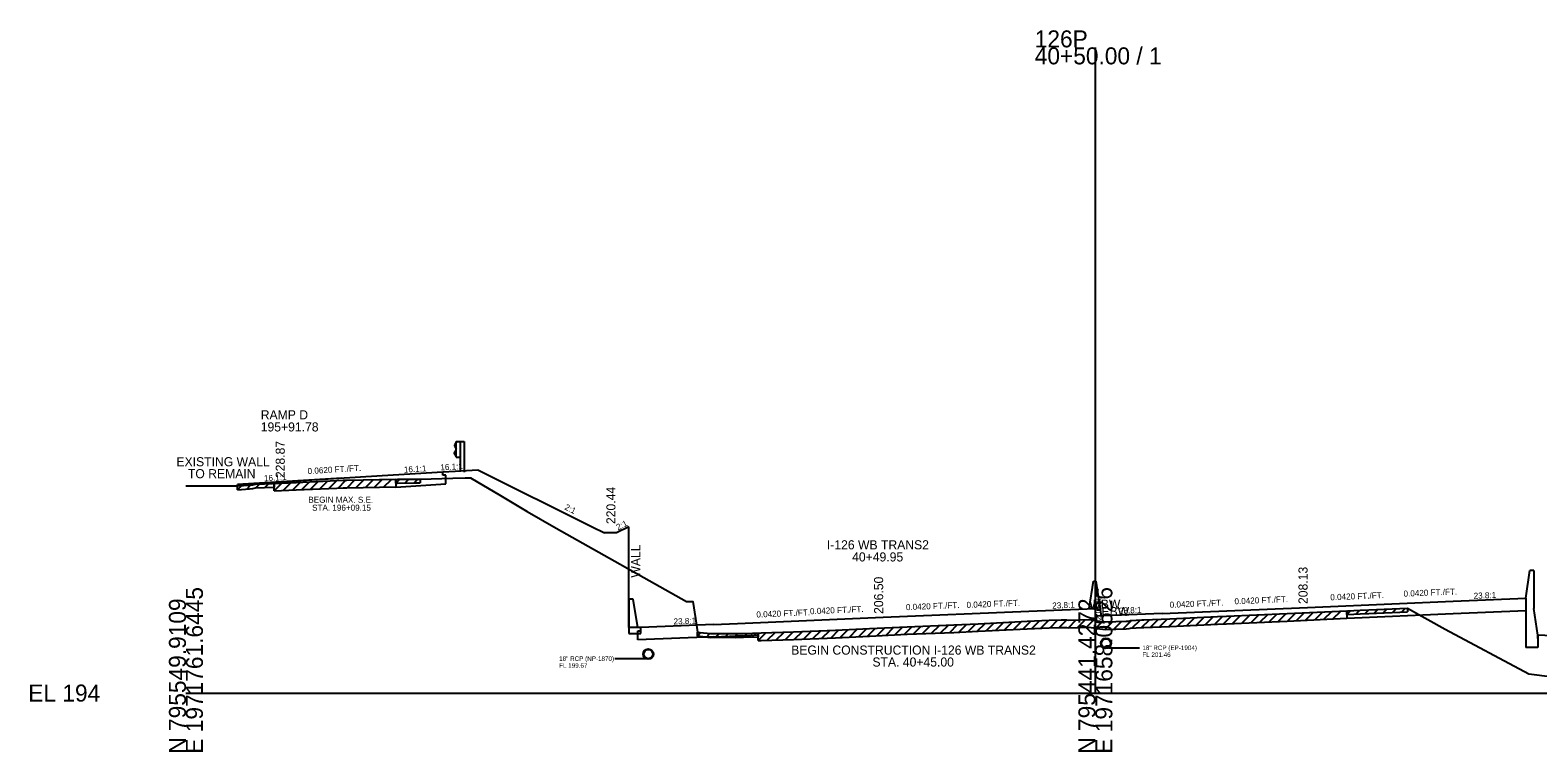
# Model space of a CAD drawing. Extents: x -161 to 1970889, y -4362 to 797231.
# Drawn here: x 974.3 to 1223, y 2990.3 to 3109.3 of the extents above; entities that cross this region are included whole.
import ezdxf

# ---------------------------------------------------------------- set-up
doc = ezdxf.new("R2010")
doc.units = 0
for name, color, linetype in [('RD_GPK_XS_Cell', 7, 'Continuous'), ('RD_XS_Base', 7, 'Continuous'), ('RD_XS_Box', 7, 'Continuous'), ('RD_XS_EarthShd', 7, 'Continuous'), ('RD_XS_ExGround', 7, 'Continuous'), ('RD_XS_ExPaveRet', 7, 'Continuous'), ('RD_XS_GR', 7, 'Continuous'), ('RD_XS_MedBWall', 7, 'Continuous'), ('RD_XS_Misc_Line', 7, 'Continuous'), ('RD_XS_Pave', 7, 'Continuous'), ('RD_XS_PaveOvlay', 7, 'Continuous'), ('RD_XS_PaveShd', 7, 'Continuous'), ('RD_XS_Pipe', 7, 'Continuous'), ('RD_XS_TieSlope', 7, 'Continuous'), ('RD_XS_TX_Elev_EX', 7, 'Continuous'), ('RD_XS_TX_Elev_PR', 7, 'Continuous'), ('RD_XS_TX_Misc', 7, 'Continuous'), ('RD_XS_TX_MkPT', 7, 'Continuous'), ('RD_XS_TX_Notes', 7, 'Continuous'), ('RD_XS_TX_Profile', 7, 'Continuous'), ('RD_XS_TX_ShdSlope', 7, 'Continuous'), ('RD_XS_TX_Slope', 7, 'Continuous'), ('RD_XS_TX_Station', 7, 'Continuous')]:
    doc.layers.add(name, color=color, linetype=linetype)

msp = doc.modelspace()

# ---------------------------------------------------------------- linework, layer by layer
at = {"layer": 'RD_GPK_XS_Cell'}
for p, q in [((1150, 3000), (1150, 3106.48)), ((1000, 3000), (1150, 3000)), ((1150, 3000), (1300, 3000))]:
    msp.add_line(p, q, dxfattribs=at)
at = {"layer": 'RD_XS_Base'}
for p, q in [((1042.39, 3035.93), (1042.39, 3036.49)), ((1008.53, 3034.17), (1008.53, 3034.38)), ((1034.62, 3033.96), (1042.89, 3034.48)), ((1042.89, 3035.96), (1042.39, 3035.93)), ((1042.89, 3034.48), (1042.89, 3035.96)), ((1191.46, 3012.36), (1209, 3013.1)), ((1209, 3013.1), (1221, 3013.6)), ((1074.53, 3010.24), (1075.03, 3010.26)), ((1074.53, 3008.76), (1074.53, 3010.24)), ((1087.04, 3009.28), (1074.53, 3008.76)), ((1075.03, 3010.26), (1075.03, 3010.82)), ((1087.04, 3009.28), (1091, 3009.45)), ((1091, 3009.45), (1094.36, 3009.59)), ((1222.98, 3008.99), (1222.98, 3009.55))]:
    msp.add_line(p, q, dxfattribs=at)
at = {"layer": 'RD_XS_Box'}
for p, q in [((1073.03, 3010.82), (1073.03, 3027.44)), ((1075.03, 3010.82), (1073.03, 3010.82))]:
    msp.add_line(p, q, dxfattribs=at)
at = {"layer": 'RD_XS_EarthShd'}
msp.add_line((1042.39, 3036.49), (1044.4, 3036.61), dxfattribs=at)
at = {"layer": 'RD_XS_ExGround'}
msp.add_lwpolyline([(1000, 3034.18), (1008.53, 3034.17), (1010.48, 3034.31), (1011.06, 3034.35), (1011.45, 3034.44), (1012.95, 3034.52), (1018.17, 3034.75), (1024.87, 3035.06), (1025.96, 3035.1), (1026.54, 3035.11), (1034.89, 3035.25), (1037.57, 3035.29), (1038.64, 3035.3), (1044.03, 3035.44), (1046.04, 3035.49), (1046.96, 3035.49), (1051.89, 3032.57), (1056.28, 3029.94), (1061.08, 3027.22), (1082.56, 3015.1), (1083.61, 3015.1), (1084.05, 3012.3), (1084.36, 3010.02), (1084.84, 3009.98), (1086.5, 3009.8), (1086.75, 3009.85), (1087.79, 3009.84), (1090.64, 3009.81), (1091.95, 3009.84), (1094.89, 3009.91), (1100.2, 3010.11), (1107.11, 3010.37), (1112.72, 3010.64), (1118.96, 3010.94), (1126.68, 3011.26), (1130.69, 3011.44), (1138.75, 3011.84), (1142.4, 3012.02), (1144.36, 3012.06), (1145.22, 3012.07), (1145.51, 3012.03), (1147.19, 3012.07), (1148.97, 3012.12), (1150, 3011.96), (1150.32, 3011.91), (1151.67, 3011.72), (1155.09, 3011.86), (1155.56, 3011.88), (1155.79, 3011.96), (1157.65, 3012.05), (1157.98, 3012.06), (1162.3, 3012.25), (1170.15, 3012.6), (1171.63, 3012.67), (1181.65, 3013.13), (1191.58, 3013.58), (1193.68, 3013.68), (1195.1, 3013.74), (1201.46, 3014.02), (1207.7, 3010.56), (1221.47, 3003.19), (1225.42, 3002.68)], dxfattribs=at)
at = {"layer": 'RD_XS_ExPaveRet'}
for p, q in [((1008.53, 3033.54), (1008.53, 3034.17)), ((1011.06, 3033.72), (1011.45, 3033.82)), ((1011.45, 3033.82), (1012.95, 3033.9)), ((1012.95, 3033.9), (1014.55, 3033.97)), ((1014.55, 3033.34), (1014.55, 3034.59)), ((1014.55, 3034.59), (1014.55, 3033.97)), ((1018.17, 3033.5), (1024.87, 3033.81)), ((1024.87, 3033.81), (1025.96, 3033.85)), ((1025.96, 3033.85), (1026.54, 3033.86)), ((1026.54, 3033.86), (1034.62, 3034)), ((1034.62, 3035.25), (1034.62, 3034)), ((1034.62, 3034.62), (1034.62, 3035.25)), ((1034.62, 3034.62), (1034.89, 3034.63)), ((1034.89, 3034.63), (1037.57, 3034.66)), ((1037.57, 3034.66), (1038.64, 3034.67)), ((1038.64, 3035.3), (1038.64, 3034.67)), ((1008.53, 3033.54), (1010.48, 3033.69)), ((1010.48, 3033.69), (1011.06, 3033.72)), ((1014.55, 3033.34), (1018.17, 3033.5)), ((1201.46, 3014.02), (1201.46, 3013.4)), ((1170.15, 3011.35), (1171.63, 3011.42)), ((1171.63, 3011.42), (1181.65, 3011.88)), ((1181.65, 3011.88), (1191.46, 3012.33)), ((1191.46, 3013.58), (1191.46, 3012.33)), ((1191.46, 3012.95), (1191.46, 3013.58)), ((1191.46, 3012.95), (1191.58, 3012.96)), ((1191.58, 3012.96), (1193.68, 3013.05)), ((1193.68, 3013.05), (1195.1, 3013.11)), ((1195.1, 3013.11), (1201.46, 3013.4)), ((1084.36, 3009.4), (1084.36, 3010.02)), ((1084.36, 3009.4), (1084.84, 3009.36)), ((1084.84, 3009.36), (1086.5, 3009.17)), ((1086.5, 3009.17), (1086.75, 3009.22)), ((1086.75, 3009.22), (1087.79, 3009.22)), ((1087.79, 3009.22), (1090.64, 3009.18)), ((1090.64, 3009.18), (1091.95, 3009.22)), ((1091.95, 3009.22), (1094.36, 3009.27)), ((1094.36, 3008.65), (1094.36, 3009.9)), ((1094.36, 3009.9), (1094.36, 3009.27)), ((1100.2, 3008.86), (1107.11, 3009.12)), ((1107.11, 3009.12), (1112.72, 3009.39)), ((1112.72, 3009.39), (1118.96, 3009.69)), ((1118.96, 3009.69), (1126.68, 3010.01)), ((1126.68, 3010.01), (1130.69, 3010.19)), ((1130.69, 3010.19), (1138.75, 3010.59)), ((1138.75, 3010.59), (1142.4, 3010.77)), ((1142.4, 3010.77), (1144.36, 3010.81)), ((1144.36, 3010.81), (1145.22, 3010.82)), ((1145.22, 3010.82), (1145.51, 3010.78)), ((1145.51, 3010.78), (1147.19, 3010.82)), ((1147.19, 3010.82), (1148.97, 3010.87)), ((1148.97, 3010.87), (1150, 3010.71)), ((1150, 3010.71), (1150.32, 3010.66)), ((1150.32, 3010.66), (1151.67, 3010.47)), ((1151.67, 3010.47), (1155.09, 3010.61)), ((1155.09, 3010.61), (1155.56, 3010.63)), ((1155.56, 3010.63), (1155.79, 3010.71)), ((1155.79, 3010.71), (1157.65, 3010.8)), ((1157.65, 3010.8), (1157.98, 3010.81)), ((1157.98, 3010.81), (1162.3, 3011)), ((1162.3, 3011), (1170.15, 3011.35)), ((1094.36, 3008.65), (1094.89, 3008.66)), ((1094.89, 3008.66), (1100.2, 3008.86))]:
    msp.add_line(p, q, dxfattribs=at)
at = {"layer": 'RD_XS_GR'}
for p, q in [((1044.55, 3041.32), (1044.28, 3040.88)), ((1044.55, 3041.48), (1045.21, 3041.48)), ((1044.55, 3038.92), (1044.55, 3041.48)), ((1045.21, 3041.48), (1045.88, 3041.48)), ((1045.21, 3041.48), (1045.21, 3036.54)), ((1045.88, 3041.48), (1045.88, 3036.43)), ((1044.28, 3040.88), (1044.28, 3040.77)), ((1044.28, 3040.77), (1044.55, 3040.33)), ((1044.28, 3039.63), (1044.55, 3040.07)), ((1044.28, 3039.52), (1044.28, 3039.63)), ((1044.55, 3039.08), (1044.28, 3039.52)), ((1044.55, 3038.92), (1045.21, 3038.92))]:
    msp.add_line(p, q, dxfattribs=at)
at = {"layer": 'RD_XS_MedBWall'}
for p, q in [((1221, 3015.64), (1221.67, 3020.19)), ((1222.33, 3020.19), (1221.67, 3020.19)), ((1222.33, 3020.19), (1222.33, 3013.95)), ((1149, 3013.92), (1149.67, 3018.47)), ((1149.67, 3018.47), (1150.14, 3018.47)), ((1151, 3012.7), (1150.14, 3018.47)), ((1073.78, 3015.48), (1073.03, 3015.48)), ((1073.03, 3015.48), (1073.03, 3009.82)), ((1074.53, 3010.82), (1073.78, 3015.48)), ((1221, 3015.64), (1221, 3013.6)), ((1221, 3015.2), (1221, 3007.51)), ((1222.98, 3009.55), (1222.33, 3013.95)), ((1073.03, 3009.82), (1075.03, 3009.82)), ((1075.03, 3010.82), (1074.53, 3010.82)), ((1075.03, 3009.82), (1075.03, 3010.82)), ((1222.98, 3009.55), (1222.98, 3007.51)), ((1222.98, 3007.51), (1221, 3007.51))]:
    msp.add_line(p, q, dxfattribs=at)
at = {"layer": 'RD_XS_Misc_Line'}
for p, q in [((1008.53, 3033.54), (1009.21, 3034.22)), ((1010.03, 3033.65), (1010.71, 3034.33)), ((1011.54, 3033.82), (1012.2, 3034.48)), ((1013.04, 3033.9), (1013.7, 3034.56)), ((1014.55, 3033.34), (1015.86, 3034.65)), ((1016.05, 3033.41), (1017.37, 3034.72)), ((1017.56, 3033.48), (1018.87, 3034.78)), ((1019.06, 3033.54), (1020.38, 3034.85)), ((1020.57, 3033.61), (1021.88, 3034.92)), ((1022.07, 3033.68), (1023.39, 3034.99)), ((1023.58, 3033.75), (1024.89, 3035.06)), ((1025.09, 3033.81), (1026.39, 3035.11)), ((1026.59, 3033.86), (1027.87, 3035.14)), ((1028.1, 3033.89), (1029.37, 3035.16)), ((1029.6, 3033.91), (1030.88, 3035.19)), ((1031.11, 3033.94), (1032.38, 3035.21)), ((1032.61, 3033.96), (1033.89, 3035.23)), ((1034.62, 3034.62), (1035.26, 3035.26)), ((1036.13, 3034.64), (1036.76, 3035.28)), ((1037.63, 3034.66), (1038.27, 3035.3)), ((1198.98, 3013.29), (1199.64, 3013.94)), ((1200.49, 3013.35), (1201.15, 3014.01)), ((1128.98, 3010.11), (1130.3, 3011.42)), ((1130.49, 3010.18), (1131.81, 3011.49)), ((1131.99, 3010.25), (1133.31, 3011.57)), ((1133.5, 3010.32), (1134.82, 3011.64)), ((1135, 3010.4), (1136.33, 3011.72)), ((1136.51, 3010.48), (1137.83, 3011.79)), ((1138.02, 3010.55), (1139.34, 3011.87)), ((1139.52, 3010.63), (1140.84, 3011.94)), ((1141.03, 3010.7), (1142.35, 3012.02)), ((1142.53, 3010.77), (1143.81, 3012.05)), ((1144.04, 3010.8), (1145.3, 3012.06)), ((1145.54, 3010.78), (1146.82, 3012.06)), ((1147.05, 3010.81), (1148.34, 3012.1)), ((1148.55, 3010.86), (1149.71, 3012.01)), ((1150.06, 3010.7), (1151.16, 3011.8)), ((1151.56, 3010.49), (1152.85, 3011.77)), ((1153.07, 3010.53), (1154.37, 3011.83)), ((1154.57, 3010.59), (1155.96, 3011.97)), ((1156.08, 3010.73), (1157.39, 3012.04)), ((1157.58, 3010.79), (1158.9, 3012.1)), ((1159.09, 3010.86), (1160.4, 3012.17)), ((1160.59, 3010.93), (1161.91, 3012.24)), ((1162.1, 3011), (1163.41, 3012.3)), ((1163.61, 3011.06), (1164.92, 3012.37)), ((1165.11, 3011.13), (1166.42, 3012.44)), ((1166.62, 3011.19), (1167.93, 3012.5)), ((1168.12, 3011.26), (1169.43, 3012.57)), ((1169.63, 3011.33), (1170.94, 3012.64)), ((1171.13, 3011.39), (1172.45, 3012.71)), ((1172.64, 3011.46), (1173.95, 3012.78)), ((1174.14, 3011.53), (1175.46, 3012.85)), ((1175.65, 3011.6), (1176.96, 3012.91)), ((1177.15, 3011.67), (1178.47, 3012.98)), ((1178.66, 3011.74), (1179.97, 3013.05)), ((1180.16, 3011.81), (1181.48, 3013.12)), ((1181.67, 3011.88), (1182.98, 3013.19)), ((1183.17, 3011.95), (1184.49, 3013.26)), ((1184.68, 3012.02), (1185.99, 3013.33)), ((1186.18, 3012.09), (1187.5, 3013.4)), ((1187.69, 3012.16), (1189, 3013.46)), ((1189.19, 3012.22), (1190.51, 3013.53)), ((1191.46, 3012.95), (1192.11, 3013.61)), ((1192.96, 3013.02), (1193.62, 3013.67)), ((1194.47, 3013.08), (1195.12, 3013.74)), ((1195.97, 3013.15), (1196.63, 3013.81)), ((1197.48, 3013.22), (1198.14, 3013.87)), ((1084.36, 3009.4), (1084.94, 3009.97)), ((1085.87, 3009.24), (1086.43, 3009.81)), ((1087.37, 3009.22), (1088, 3009.84)), ((1088.88, 3009.2), (1089.5, 3009.82)), ((1090.38, 3009.18), (1091.02, 3009.82)), ((1091.89, 3009.21), (1092.53, 3009.85)), ((1093.39, 3009.25), (1094.04, 3009.89)), ((1094.36, 3008.65), (1095.66, 3009.94)), ((1095.87, 3008.7), (1097.17, 3010)), ((1097.37, 3008.76), (1098.68, 3010.06)), ((1098.88, 3008.81), (1100.18, 3010.11)), ((1100.38, 3008.87), (1101.69, 3010.17)), ((1101.89, 3008.93), (1103.19, 3010.23)), ((1103.39, 3008.98), (1104.7, 3010.28)), ((1104.9, 3009.04), (1106.2, 3010.34)), ((1106.4, 3009.1), (1107.71, 3010.4)), ((1107.91, 3009.16), (1109.23, 3010.47)), ((1109.42, 3009.23), (1110.73, 3010.54)), ((1110.92, 3009.3), (1112.24, 3010.61)), ((1112.43, 3009.37), (1113.74, 3010.69)), ((1113.93, 3009.45), (1115.25, 3010.76)), ((1115.44, 3009.52), (1116.76, 3010.84)), ((1116.94, 3009.6), (1118.26, 3010.91)), ((1118.45, 3009.67), (1119.76, 3010.98)), ((1119.95, 3009.74), (1121.26, 3011.04)), ((1121.46, 3009.8), (1122.77, 3011.1)), ((1122.96, 3009.86), (1124.27, 3011.16)), ((1124.47, 3009.92), (1125.78, 3011.22)), ((1125.97, 3009.98), (1127.28, 3011.28)), ((1127.48, 3010.04), (1128.79, 3011.35))]:
    msp.add_line(p, q, dxfattribs=at)
at = {"layer": 'RD_XS_Pave'}
for p, q in [((1016.3, 3034.87), (1032.36, 3035.86)), ((1161, 3013.12), (1185, 3014.13)), ((1185, 3014.13), (1209, 3015.14)), ((1087.04, 3011.32), (1091, 3011.49)), ((1091, 3011.49), (1115, 3012.5)), ((1115, 3012.5), (1139, 3013.5))]:
    msp.add_line(p, q, dxfattribs=at)
at = {"layer": 'RD_XS_PaveOvlay'}
for p, q in [((1011.06, 3034.35), (1008.53, 3034.17)), ((1011.45, 3034.44), (1011.06, 3034.35)), ((1014.55, 3034.59), (1011.45, 3034.44)), ((1014.55, 3034.59), (1018.17, 3034.75)), ((1018.17, 3034.75), (1024.87, 3035.06)), ((1024.87, 3035.06), (1025.96, 3035.1)), ((1025.96, 3035.1), (1026.54, 3035.11)), ((1026.54, 3035.11), (1034.62, 3035.25)), ((1034.62, 3035.25), (1034.62, 3033.96)), ((1126.68, 3011.26), (1130.69, 3011.44)), ((1130.69, 3011.44), (1138.75, 3011.84)), ((1138.75, 3011.84), (1142.4, 3012.02)), ((1142.4, 3012.02), (1144.36, 3012.06)), ((1144.36, 3012.06), (1145.22, 3012.07)), ((1145.22, 3012.07), (1145.51, 3012.03)), ((1145.51, 3012.03), (1147.19, 3012.07)), ((1147.19, 3012.07), (1148.97, 3012.12)), ((1148.97, 3012.12), (1150, 3011.96)), ((1150, 3011.96), (1150.32, 3011.91)), ((1150.32, 3011.91), (1151.67, 3011.72)), ((1151.67, 3011.72), (1155.09, 3011.86)), ((1155.09, 3011.86), (1155.56, 3011.88)), ((1155.56, 3011.88), (1155.79, 3011.96)), ((1155.79, 3011.96), (1157.65, 3012.05)), ((1157.65, 3012.05), (1157.98, 3012.06)), ((1157.98, 3012.06), (1162.3, 3012.25)), ((1162.3, 3012.25), (1170.15, 3012.6)), ((1170.15, 3012.6), (1171.63, 3012.67)), ((1171.63, 3012.67), (1181.65, 3013.13)), ((1181.65, 3013.13), (1191.46, 3013.58)), ((1191.46, 3013.58), (1191.46, 3012.36)), ((1094.36, 3009.9), (1094.89, 3009.91)), ((1094.36, 3009.9), (1094.36, 3009.59)), ((1094.89, 3009.91), (1100.2, 3010.11)), ((1100.2, 3010.11), (1107.11, 3010.37)), ((1107.11, 3010.37), (1112.72, 3010.64)), ((1112.72, 3010.64), (1118.96, 3010.94)), ((1118.96, 3010.94), (1126.68, 3011.26))]:
    msp.add_line(p, q, dxfattribs=at)
at = {"layer": 'RD_XS_PaveShd'}
for p, q in [((1032.36, 3035.86), (1042.39, 3036.49)), ((1025.72, 3035.45), (1008.53, 3034.38)), ((1139, 3013.5), (1150, 3013.97)), ((1150, 3012.65), (1150, 3013.97)), ((1209, 3015.14), (1221, 3015.64)), ((1161, 3013.12), (1150, 3012.66)), ((1087.04, 3011.32), (1075.03, 3010.82)), ((1232.98, 3009.09), (1222.98, 3009.55))]:
    msp.add_line(p, q, dxfattribs=at)
at = {"layer": 'RD_XS_Pipe'}
for p, q in [((1152.25, 3007.46), (1157.25, 3007.46)), ((1075.76, 3005.67), (1070.76, 3005.67))]:
    msp.add_line(p, q, dxfattribs=at)
for centre, radius in [((1151.75, 3008.21), 0.85), ((1151.75, 3008.21), 0.75), ((1076.26, 3006.42), 0.85), ((1076.26, 3006.42), 0.75)]:
    msp.add_circle(centre, radius, dxfattribs=at)
at = {"layer": 'RD_XS_TieSlope'}
for p, q in [((1044.4, 3036.61), (1048.16, 3036.84)), ((1048.16, 3036.84), (1067.03, 3027.44)), ((1067.03, 3027.44), (1069.03, 3026.44)), ((1071.03, 3026.44), (1069.03, 3026.44)), ((1073.03, 3027.44), (1071.03, 3026.44))]:
    msp.add_line(p, q, dxfattribs=at)

# ---------------------------------------------------------------- texts
at = {"layer": 'RD_GPK_XS_Cell'}
for s, p in [('126P', (1140, 3106.48)), ('40+50.00 / 1', (1140, 3103.68)), ('EL 194', (974, 2998.6))]:
    msp.add_text(s, height=2.8, dxfattribs=at).set_placement(p)
for s, p in [('E 1971761.6445', (1002.8, 2990)), ('E 1971658.0526', (1152.8, 2990)), ('N 795549.9109', (1000, 2990)), ('N 795441.4272', (1150, 2990))]:
    msp.add_text(s, height=2.8, rotation=90, dxfattribs=at).set_placement(p)
at = {"layer": 'RD_XS_Pipe'}
for s, p in [('18" RCP (EP-1904)', (1157.75, 3007.09)), ('FL 201.46', (1157.75, 3005.96)), ('18" RCP (NP-1870)', (1061.56, 3005.3)), ('FL 199.67', (1061.56, 3004.17))]:
    msp.add_text(s, height=0.75, dxfattribs=at).set_placement(p)
at = {"layer": 'RD_XS_TX_Elev_EX'}
msp.add_text('205.96', height=1, rotation=90, dxfattribs=at).set_placement((1151, 3011.96))
at = {"layer": 'RD_XS_TX_Elev_PR'}
for s, p in [(' 228.87', (1016.3, 3034.89)), (' 206.50', (1115, 3012.5)), (' 208.13', (1185, 3014.13))]:
    msp.add_text(s, height=1.5, rotation=90, dxfattribs=at).set_placement(p)
at = {"layer": 'RD_XS_TX_Misc'}
msp.add_text('220.44', height=1.5, rotation=90, dxfattribs=at).set_placement((1070.84, 3027.87))
at = {"layer": 'RD_XS_TX_MkPT'}
for s, p in [('WBW', (1149, 3013.92)), ('EBW', (1151, 3012.7))]:
    msp.add_text(s, height=1.5, dxfattribs=at).set_placement(p)
at = {"layer": 'RD_XS_TX_Notes'}
for s, height, p in [('EXISTING WALL', 1.5, (998.44, 3037.4)), ('TO REMAIN', 1.5, (1000.33, 3035.43)), ('BEGIN MAX. S.E.', 1, (1020.19, 3031.38)), ('STA. 196+09.15', 1, (1020.81, 3030.07)), ('BEGIN CONSTRUCTION I-126 WB TRANS2', 1.5, (1099.83, 3006.34)), ('STA. 40+45.00', 1.5, (1113.23, 3004.37))]:
    msp.add_text(s, height=height, dxfattribs=at).set_placement(p)
msp.add_text('WALL', height=1.5, rotation=90, dxfattribs=at).set_placement((1074.93, 3019.04))
at = {"layer": 'RD_XS_TX_Profile'}
for s, rotation, p in [('16.1:1', 3.5453, (1035.98, 3036.34)), ('23.8:1', 2.405, (1212.41, 3015.53)), ('23.8:1', 2.405, (1142.91, 3013.92)), ('23.8:1', 2.405, (1153.91, 3013.08)), ('23.8:1', 2.4033, (1080.45, 3011.3))]:
    msp.add_text(s, height=1, rotation=rotation, dxfattribs=at).set_placement(p)
at = {"layer": 'RD_XS_TX_ShdSlope'}
msp.add_text('16.1:1', height=1, rotation=3.5453, dxfattribs=at).set_placement((1042, 3036.71))
at = {"layer": 'RD_XS_TX_Slope'}
for s, rotation, p in [('0.0620 FT./FT.', 3.5453, (1020.1, 3036.1)), ('16.1:1', 3.5447, (1012.9, 3034.91)), ('2:1', 333.5094, (1062.36, 3030.33)), ('2:1', 26.5651, (1071.27, 3026.82)), ('0.0420 FT./FT.', 2.405, (1188.77, 3015.29)), ('0.0420 FT./FT.', 2.405, (1200.85, 3015.89)), ('0.0420 FT./FT.', 2.4033, (1102.95, 3012.99)), ('0.0420 FT./FT.', 2.405, (1118.77, 3013.66)), ('0.0420 FT./FT.', 2.405, (1128.77, 3014.03)), ('0.0420 FT./FT.', 2.405, (1162.28, 3014.05)), ('0.0420 FT./FT.', 2.405, (1172.96, 3014.63)), ('0.0420 FT./FT.', 2.405, (1094.11, 3012.45))]:
    msp.add_text(s, height=1, rotation=rotation, dxfattribs=at).set_placement(p)
at = {"layer": 'RD_XS_TX_Station'}
for s, p in [('RAMP D', (1012.34, 3045.14)), ('195+91.78', (1012.34, 3043.14)), ('I-126 WB TRANS2', (1105.72, 3023.7)), ('40+49.95', (1109.88, 3021.7))]:
    msp.add_text(s, height=1.5, dxfattribs=at).set_placement(p)

doc.saveas('drawing.dxf')
